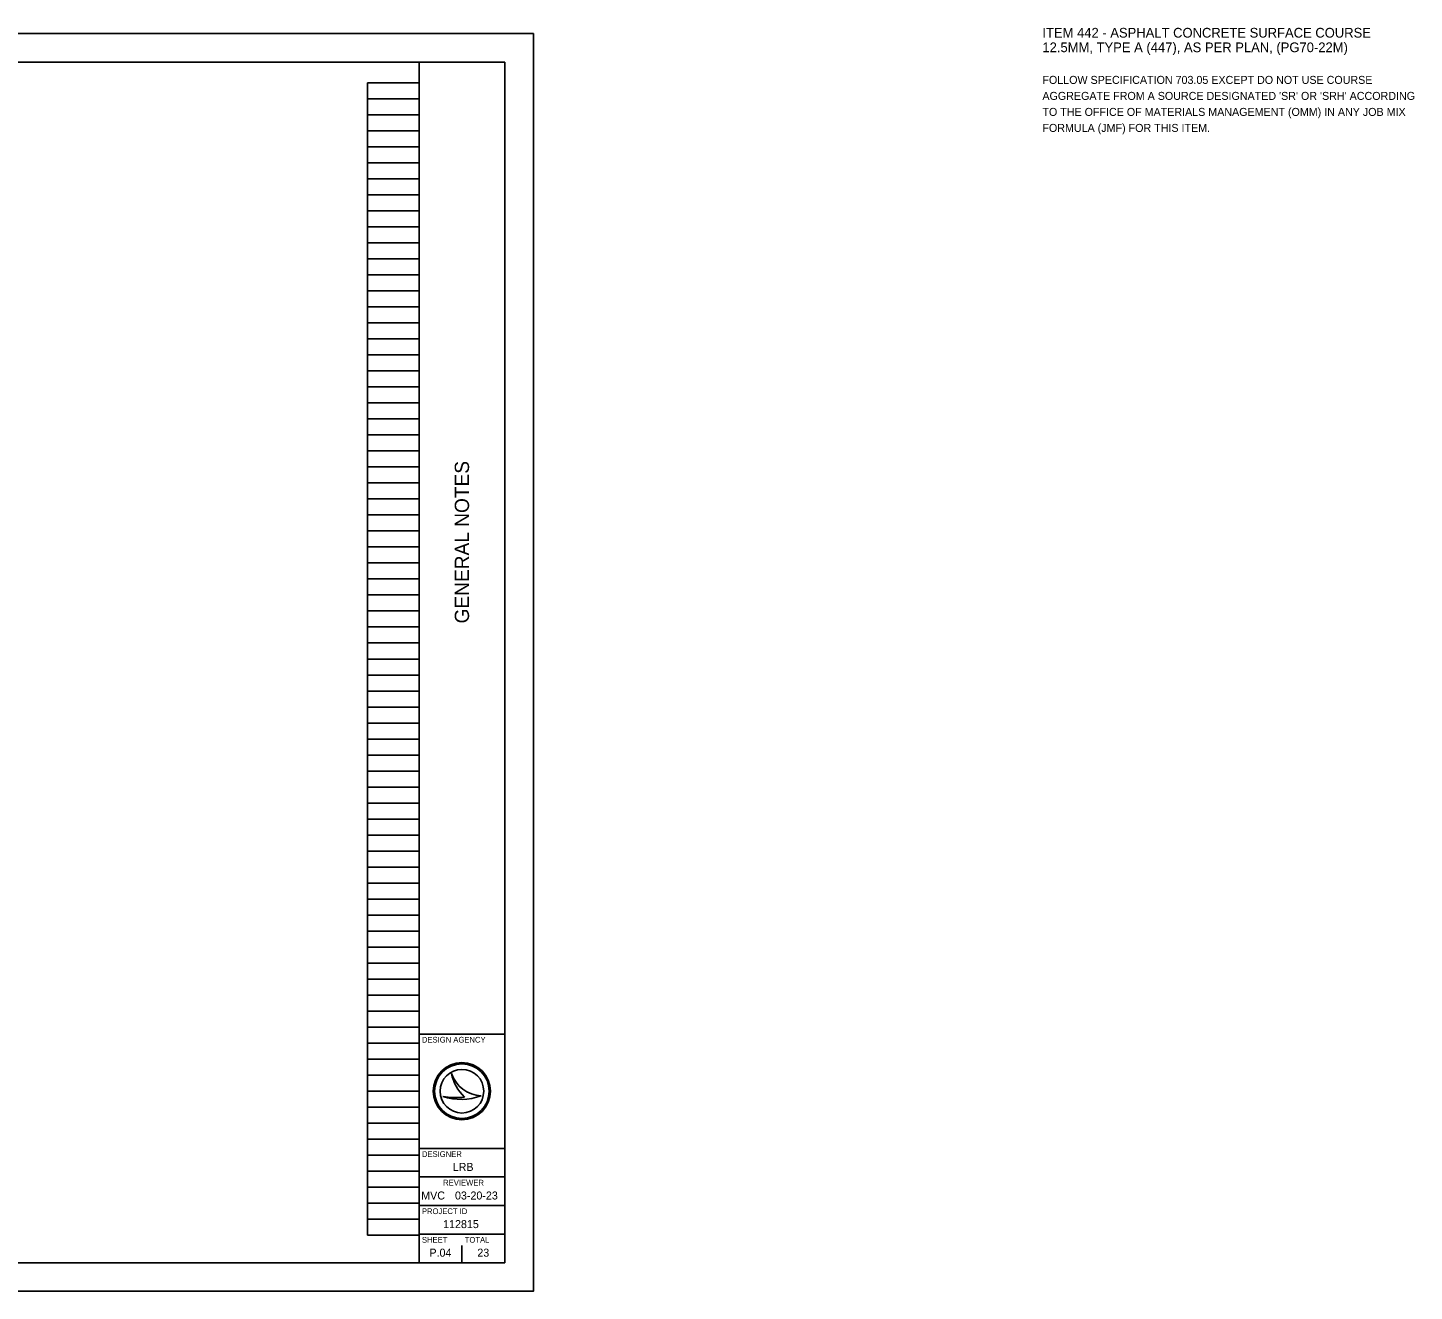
# Model space of a CAD drawing. Extents: x 0 to 49.4, y 0 to 22.1.
# Drawn here: x 25.15 to 49.41, y 0 to 22.1 of the extents above; entities that cross this region are included whole.
import ezdxf

# ---------------------------------------------------------------- set-up
doc = ezdxf.new("R2010")
doc.units = 0
for name, color, linetype in [('SH_Border', 7, 'Continuous'), ('SH_Cut_Line', 7, 'Continuous'), ('SH_Data', 7, 'Continuous'), ('SH_Text', 7, 'Continuous')]:
    doc.layers.add(name, color=color, linetype=linetype)

msp = doc.modelspace()

# ---------------------------------------------------------------- linework, layer by layer
at = {"layer": 'SH_Border'}
for p, q in [((32, 0.5), (32, 21.5)), ((32, 4.5), (33.5, 4.5)), ((32, 2.5), (33.5, 2.5)), ((32, 2), (33.5, 2)), ((32, 1.5), (33.5, 1.5)), ((32, 1), (33.5, 1))]:
    msp.add_line(p, q, dxfattribs=at)
msp.add_lwpolyline([(1.5, 21.5), (33.5, 21.5), (33.5, 0.5), (1.5, 0.5)], close=True, dxfattribs=at)
at = {"layer": 'SH_Cut_Line'}
msp.add_lwpolyline([(0, 0), (34, 0), (34, 22), (0, 22)], close=True, dxfattribs=at)
at = {"layer": 'SH_Data'}
for p, q in [((31.1, 0.98), (31.1, 21.14)), ((31.1, 21.14), (32, 21.14)), ((32, 0.98), (32, 21.14)), ((31.1, 20.86), (32, 20.86)), ((31.1, 20.58), (32, 20.58)), ((31.1, 20.3), (32, 20.3)), ((31.1, 20.02), (32, 20.02)), ((31.1, 19.74), (32, 19.74)), ((31.1, 19.46), (32, 19.46)), ((31.1, 19.18), (32, 19.18)), ((31.1, 18.9), (32, 18.9)), ((31.1, 18.62), (32, 18.62)), ((31.1, 18.34), (32, 18.34)), ((31.1, 18.06), (32, 18.06)), ((31.1, 17.78), (32, 17.78)), ((31.1, 17.5), (32, 17.5)), ((31.1, 17.22), (32, 17.22)), ((31.1, 16.94), (32, 16.94)), ((31.1, 16.66), (32, 16.66)), ((31.1, 16.38), (32, 16.38)), ((31.1, 16.1), (32, 16.1)), ((31.1, 15.82), (32, 15.82)), ((31.1, 15.54), (32, 15.54)), ((31.1, 15.26), (32, 15.26)), ((31.1, 14.98), (32, 14.98)), ((31.1, 14.7), (32, 14.7)), ((31.1, 14.42), (32, 14.42)), ((31.1, 14.14), (32, 14.14)), ((31.1, 13.86), (32, 13.86)), ((31.1, 13.58), (32, 13.58)), ((31.1, 13.3), (32, 13.3)), ((31.1, 13.02), (32, 13.02)), ((31.1, 12.74), (32, 12.74)), ((31.1, 12.46), (32, 12.46)), ((31.1, 12.18), (32, 12.18)), ((31.1, 11.9), (32, 11.9)), ((31.1, 11.62), (32, 11.62)), ((31.1, 11.34), (32, 11.34)), ((31.1, 11.06), (32, 11.06)), ((31.1, 10.78), (32, 10.78)), ((31.1, 10.5), (32, 10.5)), ((31.1, 10.22), (32, 10.22)), ((31.1, 9.94), (32, 9.94)), ((31.1, 9.66), (32, 9.66)), ((31.1, 9.38), (32, 9.38)), ((31.1, 9.1), (32, 9.1)), ((31.1, 8.82), (32, 8.82)), ((31.1, 8.54), (32, 8.54)), ((31.1, 8.26), (32, 8.26)), ((31.1, 7.98), (32, 7.98)), ((31.1, 7.7), (32, 7.7)), ((31.1, 7.42), (32, 7.42)), ((31.1, 7.14), (32, 7.14)), ((31.1, 6.86), (32, 6.86)), ((31.1, 6.58), (32, 6.58)), ((31.1, 6.3), (32, 6.3)), ((31.1, 6.02), (32, 6.02)), ((31.1, 5.74), (32, 5.74)), ((31.1, 5.46), (32, 5.46)), ((31.1, 5.18), (32, 5.18)), ((31.1, 4.9), (32, 4.9)), ((31.1, 4.62), (32, 4.62)), ((31.1, 4.34), (32, 4.34)), ((31.1, 4.06), (32, 4.06)), ((31.1, 3.78), (32, 3.78)), ((32.567, 3.81), (32.567, 3.81)), ((31.1, 3.5), (32, 3.5)), ((32.417, 3.41), (32.417, 3.41)), ((32.75, 3.5), (32.75, 3.5)), ((33.087, 3.419), (33.087, 3.419)), ((31.1, 3.22), (32, 3.22)), ((31.1, 2.94), (32, 2.94)), ((31.1, 2.66), (32, 2.66)), ((31.1, 2.38), (32, 2.38)), ((31.1, 2.1), (32, 2.1)), ((31.1, 1.82), (32, 1.82)), ((31.1, 1.54), (32, 1.54)), ((31.1, 1.26), (32, 1.26)), ((31.1, 0.98), (32, 0.98)), ((32.75, 0.5), (32.75, 0.8)), ((32.375, 0.675), (32.375, 0.675))]:
    msp.add_line(p, q, dxfattribs=at)
for radius in [0.5, 0.477, 0.477, 0.382]:
    msp.add_circle((32.75, 3.5), radius, dxfattribs=at)
for centre, radius, start, end in [((33.116, 3.998), 0.58, 198.9257, 198.9319), ((33.347, 3.97), 0.796, 191.6379, 191.6421), ((33.116, 3.998), 0.58, 198.9319, 267.1657), ((33.347, 3.97), 0.796, 191.6421, 226.0947), ((32.739, 4.37), 1.013, 251.4576, 290.0832), ((32.648, 4.654), 1.266, 259.4964, 259.4995), ((32.739, 4.37), 1.013, 251.4527, 251.4576), ((32.648, 4.654), 1.266, 259.4995, 276.6672)]:
    msp.add_arc(centre, radius, start, end, dxfattribs=at)

# ---------------------------------------------------------------- texts
msp.add_text('GENERAL NOTES', height=0.25, rotation=90, dxfattribs=at).set_placement((32.875, 11.682))
for s, height, p in [('DESIGN AGENCY', 0.1, (32.05, 4.35)), ('DESIGNER', 0.1, (32.05, 2.35)), ('LRB', 0.14, (32.589, 2.105)), ('REVIEWER', 0.1, (32.422, 1.85)), ('MVC', 0.14, (32.038, 1.605)), ('03-20-23', 0.14, (32.629, 1.605)), ('PROJECT ID', 0.1, (32.05, 1.35)), ('112815', 0.14, (32.421, 1.105)), ('SHEET', 0.1, (32.05, 0.85)), ('P.04', 0.14, (32.182, 0.605)), ('TOTAL', 0.1, (32.8, 0.85)), ('23', 0.14, (33.02, 0.605))]:
    msp.add_text(s, height=height, dxfattribs=at).set_placement(p)
at = {"layer": 'SH_Text'}
for s, height, p in [('ITEM 442 - ASPHALT CONCRETE SURFACE COURSE ', 0.17, (42.906, 21.93)), ('12.5MM, TYPE A (447), AS PER PLAN, (PG70-22M)', 0.17, (42.906, 21.675)), ('FOLLOW SPECIFICATION 703.05 EXCEPT DO NOT USE COURSE ', 0.14, (42.906, 21.12)), ("AGGREGATE FROM A SOURCE DESIGNATED 'SR' OR 'SRH' ACCORDING ", 0.14, (42.906, 20.84)), ('TO THE OFFICE OF MATERIALS MANAGEMENT (OMM) IN ANY JOB MIX ', 0.14, (42.906, 20.56)), ('FORMULA (JMF) FOR THIS ITEM. ', 0.14, (42.906, 20.28))]:
    msp.add_text(s, height=height, dxfattribs=at).set_placement(p)

doc.saveas('drawing.dxf')
